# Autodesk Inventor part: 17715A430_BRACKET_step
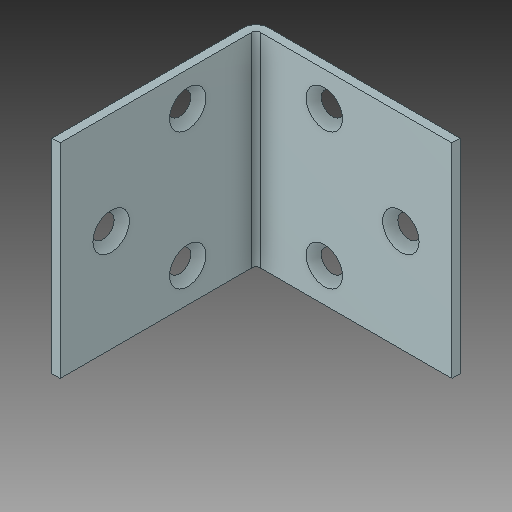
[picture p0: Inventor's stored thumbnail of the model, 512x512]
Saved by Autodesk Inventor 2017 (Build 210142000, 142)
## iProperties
Created: 2017-05
Part Number: 17715A430_BRACKET_step
Material: Generic
Document SubType Name: Modeling
Designer: Savy
Density: 1 g/cm^3
Appearance: Default
Author: Savy
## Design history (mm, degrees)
feature "SOLID1"
body "Solid1"
